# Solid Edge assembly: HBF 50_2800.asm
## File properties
Title: Zylinder
Author: bmolnar
Template: iso assembly.asm
Last saved by: bmolnar
Revision: 58
Application: Solid Edge
Username: bmolnar
Dokumentum tartalom típus: 1
Document Number: HBF 50/2800
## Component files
Kit.par
Profilrohr.par
Kolbenstange_1.par
Mutter.par
Kolbenstange_2.par
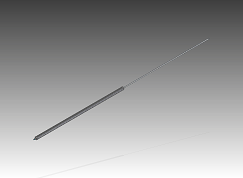
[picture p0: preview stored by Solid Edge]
